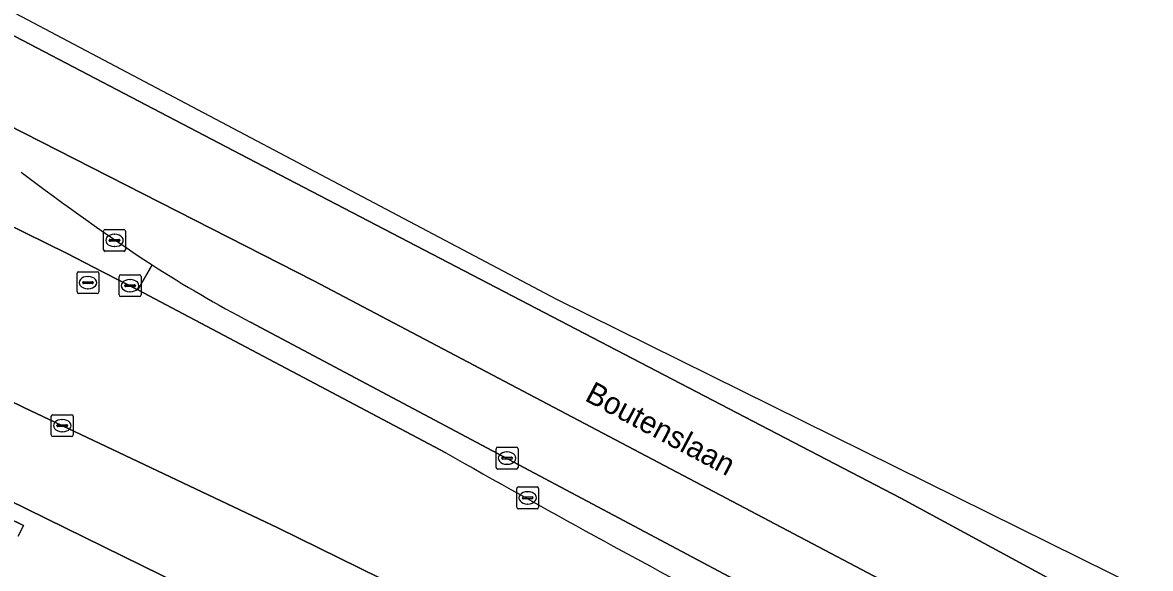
# Model space of a CAD drawing. Extents: x 160157 to 160921, y 381516 to 382045.
# Drawn here: x 160441.8 to 160493.3, y 381975.7 to 382000.7 of the extents above; entities that cross this region are included whole.
import ezdxf

# ---------------------------------------------------------------- set-up
doc = ezdxf.new("R2010")
doc.units = 0
for name, color, linetype in [('IMGEO_Berm_open', 7, 'Continuous'), ('IMGEO_Erf', 7, 'Continuous'), ('IMGEO_Kolk', 7, 'Continuous'), ('IMGEO_Openbare_ruimte_label', 7, 'Continuous'), ('IMGEO_Pand', 7, 'Continuous'), ('IMGEO_Rijbaan_lokaal_open', 7, 'Continuous'), ('IMGEO_Rijbaan_regionaal_gesloten', 7, 'Continuous'), ('IMGEO_Rioolput', 7, 'Continuous'), ('IMGEO_Verkeerseiland_groen', 7, 'Continuous'), ('IMGEO_Voetpad_open', 7, 'Continuous')]:
    doc.layers.add(name, color=color, linetype=linetype)

msp = doc.modelspace()

# ---------------------------------------------------------------- linework, layer by layer
at = {"layer": 'IMGEO_Berm_open'}
for points in [[(160447.738, 381989.6), (160447.085, 381988.461), (160461.163, 381981.009)], [(160474.789, 381973.536), (160500, 381960.326), (160522.19, 381948.698), (160522.991, 381948.067), (160523.654, 381949.34), (160513.241, 381954.71), (160502.844, 381960.063), (160500, 381961.576), (160494.279, 381964.619), (160452.239, 381986.977)]]:
    msp.add_lwpolyline(points, dxfattribs=at)
for centre, radius, start, end in [((160482.414, 382043.931), 64.454, 237.45198, 242.08423), ((160725.425, 382446.696), 535.443, 240.42651, 242.08952)]:
    msp.add_arc(centre, radius, start, end, dxfattribs=at)
at = {"layer": 'IMGEO_Erf'}
for points in [[(160499.613, 381930.156), (160499.728, 381932.119), (160500, 381935.142), (160500.334, 381938.849), (160504.716, 381938.591), (160504.68, 381937.97), (160512.664, 381937.5), (160512.953, 381943.6), (160501.945, 381949.103), (160497.103, 381938.644), (160494.055, 381942.41), (160498.282, 381950.798), (160402.448, 381997.893)], [(160426.28, 381985.318), (160441.863, 381977.687), (160441.625, 381977.202)]]:
    msp.add_lwpolyline(points, dxfattribs=at)
at = {"layer": 'IMGEO_Kolk'}
for p, q in [((160445.523, 381990.294), (160445.523, 381991.146)), ((160445.598, 381991.22), (160446.45, 381991.22)), ((160446.524, 381991.146), (160446.524, 381990.294)), ((160445.782, 381990.714), (160445.782, 381990.726)), ((160446.22, 381990.677), (160445.822, 381990.677)), ((160445.825, 381990.763), (160446.223, 381990.763)), ((160446.011, 381991), (160446.036, 381991)), ((160446.266, 381990.726), (160446.266, 381990.714)), ((160446.45, 381990.22), (160445.598, 381990.22)), ((160446.034, 381990.44), (160446.009, 381990.44)), ((160446.234, 381988.225), (160446.234, 381989.077)), ((160446.309, 381989.151), (160447.161, 381989.151)), ((160447.235, 381989.077), (160447.235, 381988.225)), ((160446.493, 381988.645), (160446.493, 381988.657)), ((160446.931, 381988.608), (160446.533, 381988.608)), ((160446.536, 381988.694), (160446.934, 381988.694)), ((160446.722, 381988.931), (160446.747, 381988.931)), ((160446.977, 381988.657), (160446.977, 381988.645)), ((160447.161, 381988.151), (160446.309, 381988.151)), ((160446.745, 381988.371), (160446.72, 381988.371)), ((160443.136, 381981.83), (160443.136, 381982.682)), ((160443.211, 381982.756), (160444.063, 381982.756)), ((160443.624, 381982.536), (160443.649, 381982.536)), ((160444.137, 381982.682), (160444.137, 381981.83)), ((160443.395, 381982.25), (160443.395, 381982.262)), ((160443.833, 381982.213), (160443.435, 381982.213)), ((160443.438, 381982.299), (160443.836, 381982.299)), ((160443.647, 381981.976), (160443.622, 381981.976)), ((160443.879, 381982.262), (160443.879, 381982.25)), ((160444.063, 381981.756), (160443.211, 381981.756)), ((160463.454, 381980.346), (160463.454, 381981.198)), ((160463.529, 381981.272), (160464.381, 381981.272)), ((160463.942, 381981.052), (160463.967, 381981.052)), ((160464.455, 381981.198), (160464.455, 381980.346)), ((160463.713, 381980.766), (160463.713, 381980.778)), ((160464.151, 381980.729), (160463.753, 381980.729)), ((160463.756, 381980.815), (160464.154, 381980.815)), ((160463.965, 381980.492), (160463.94, 381980.492)), ((160464.197, 381980.778), (160464.197, 381980.766)), ((160464.381, 381980.272), (160463.529, 381980.272)), ((160464.396, 381978.529), (160464.396, 381979.381)), ((160464.471, 381979.455), (160465.323, 381979.455)), ((160465.397, 381979.381), (160465.397, 381978.529)), ((160464.655, 381978.949), (160464.655, 381978.961)), ((160465.093, 381978.912), (160464.695, 381978.912)), ((160464.698, 381978.998), (160465.096, 381978.998)), ((160464.884, 381979.235), (160464.909, 381979.235)), ((160465.139, 381978.961), (160465.139, 381978.949)), ((160465.323, 381978.455), (160464.471, 381978.455)), ((160464.907, 381978.675), (160464.882, 381978.675))]:
    msp.add_line(p, q, dxfattribs=at)
for points in [[(160445.523, 381990.294), (160445.523, 381991.146)], [(160445.598, 381991.22), (160446.45, 381991.22)], [(160446.524, 381991.146), (160446.524, 381990.294)], [(160446.45, 381990.22), (160445.598, 381990.22)], [(160446.234, 381988.225), (160446.234, 381989.077)], [(160446.309, 381989.151), (160447.161, 381989.151)], [(160447.235, 381989.077), (160447.235, 381988.225)], [(160447.161, 381988.151), (160446.309, 381988.151)], [(160443.136, 381981.83), (160443.136, 381982.682)], [(160443.211, 381982.756), (160444.063, 381982.756)], [(160444.137, 381982.682), (160444.137, 381981.83)], [(160444.063, 381981.756), (160443.211, 381981.756)], [(160463.454, 381980.346), (160463.454, 381981.198)], [(160463.529, 381981.272), (160464.381, 381981.272)], [(160464.455, 381981.198), (160464.455, 381980.346)], [(160464.381, 381980.272), (160463.529, 381980.272)], [(160464.396, 381978.529), (160464.396, 381979.381)], [(160464.471, 381979.455), (160465.323, 381979.455)], [(160465.397, 381979.381), (160465.397, 381978.529)], [(160465.323, 381978.455), (160464.471, 381978.455)]]:
    msp.add_lwpolyline(points, dxfattribs=at)
for centre, radius, start, end in [((160445.6, 381991.144), 0.0765, 91.552, 178.448), ((160445.6, 381991.144), 0.0765, 91.552, 178.448), ((160446.448, 381991.144), 0.0765, 1.552, 88.448), ((160446.448, 381991.144), 0.0765, 1.552, 88.448), ((160445.822, 381990.723), 0.0403, 85.8775, 175.7526), ((160445.819, 381990.713), 0.0366, 178.938, 274.7102), ((160446.223, 381990.72), 0.043, 264.8664, 352.4533), ((160446.227, 381990.725), 0.0386, 1.7309, 96.639), ((160445.6, 381990.296), 0.0765, 181.552, 268.448), ((160445.6, 381990.296), 0.0765, 181.552, 268.448), ((160446.448, 381990.296), 0.0765, 271.552, 358.448), ((160446.448, 381990.296), 0.0765, 271.552, 358.448), ((160446.311, 381989.075), 0.0765, 91.552, 178.448), ((160446.311, 381989.075), 0.0765, 91.552, 178.448), ((160447.159, 381989.075), 0.0765, 1.552, 88.448), ((160447.159, 381989.075), 0.0765, 1.552, 88.448), ((160446.533, 381988.654), 0.0403, 85.8775, 175.7526), ((160446.53, 381988.644), 0.0366, 178.938, 274.7102), ((160446.934, 381988.651), 0.043, 264.8664, 352.4533), ((160446.938, 381988.656), 0.0386, 1.7309, 96.639), ((160446.311, 381988.227), 0.0765, 181.552, 268.448), ((160446.311, 381988.227), 0.0765, 181.552, 268.448), ((160447.159, 381988.227), 0.0765, 271.552, 358.448), ((160447.159, 381988.227), 0.0765, 271.552, 358.448), ((160443.213, 381982.68), 0.0765, 91.552, 178.448), ((160443.213, 381982.68), 0.0765, 91.552, 178.448), ((160444.061, 381982.68), 0.0765, 1.552, 88.448), ((160444.061, 381982.68), 0.0765, 1.552, 88.448), ((160443.435, 381982.259), 0.0403, 85.8775, 175.7526), ((160443.432, 381982.249), 0.0366, 178.938, 274.7102), ((160443.836, 381982.256), 0.043, 264.8664, 352.4533), ((160443.84, 381982.261), 0.0386, 1.7309, 96.639), ((160443.213, 381981.832), 0.0765, 181.552, 268.448), ((160443.213, 381981.832), 0.0765, 181.552, 268.448), ((160444.061, 381981.832), 0.0765, 271.552, 358.448), ((160444.061, 381981.832), 0.0765, 271.552, 358.448), ((160463.531, 381981.196), 0.0765, 91.552, 178.448), ((160463.531, 381981.196), 0.0765, 91.552, 178.448), ((160464.379, 381981.196), 0.0765, 1.552, 88.448), ((160464.379, 381981.196), 0.0765, 1.552, 88.448), ((160463.531, 381980.348), 0.0765, 181.552, 268.448), ((160463.531, 381980.348), 0.0765, 181.552, 268.448), ((160463.753, 381980.775), 0.0403, 85.8775, 175.7526), ((160463.75, 381980.765), 0.0366, 178.938, 274.7102), ((160464.154, 381980.772), 0.043, 264.8664, 352.4533), ((160464.158, 381980.777), 0.0386, 1.7309, 96.639), ((160464.379, 381980.348), 0.0765, 271.552, 358.448), ((160464.379, 381980.348), 0.0765, 271.552, 358.448), ((160464.473, 381979.379), 0.0765, 91.552, 178.448), ((160464.473, 381979.379), 0.0765, 91.552, 178.448), ((160465.321, 381979.379), 0.0765, 1.552, 88.448), ((160465.321, 381979.379), 0.0765, 1.552, 88.448), ((160464.695, 381978.958), 0.0403, 85.8775, 175.7526), ((160464.692, 381978.948), 0.0366, 178.938, 274.7102), ((160465.096, 381978.955), 0.043, 264.8664, 352.4533), ((160465.1, 381978.96), 0.0386, 1.7309, 96.639), ((160464.473, 381978.531), 0.0765, 181.552, 268.448), ((160464.473, 381978.531), 0.0765, 181.552, 268.448), ((160465.321, 381978.531), 0.0765, 271.552, 358.448), ((160465.321, 381978.531), 0.0765, 271.552, 358.448)]:
    msp.add_arc(centre, radius, start, end, dxfattribs=at)
for centre, major_axis, ratio, start_param, end_param in [((160446.01, 381990.72), (-0.387, 0.002), 0.722429, 4.712389, 7.853982), ((160446.035, 381990.72), (-0.39, 0.002), 0.717154, 1.570796, 4.712389), ((160446.721, 381988.651), (-0.387, 0.002), 0.722429, 4.712389, 7.853982), ((160446.746, 381988.651), (-0.39, 0.002), 0.717154, 1.570796, 4.712389), ((160443.623, 381982.256), (-0.387, 0.002), 0.722429, 4.712389, 7.853982), ((160443.648, 381982.256), (-0.39, 0.002), 0.717154, 1.570796, 4.712389), ((160463.941, 381980.772), (-0.387, 0.002), 0.722429, 4.712389, 7.853982), ((160463.966, 381980.772), (-0.39, 0.002), 0.717154, 1.570796, 4.712389), ((160464.883, 381978.955), (-0.387, 0.002), 0.722429, 4.712389, 7.853982), ((160464.908, 381978.955), (-0.39, 0.002), 0.717154, 1.570796, 4.712389)]:
    msp.add_ellipse(centre, major_axis=major_axis, ratio=ratio, start_param=start_param, end_param=end_param, dxfattribs=at)
at = {"layer": 'IMGEO_Pand'}
msp.add_lwpolyline([(160441.625, 381977.202), (160441.863, 381977.687), (160426.28, 381985.318)], dxfattribs=at)
at = {"layer": 'IMGEO_Rijbaan_lokaal_open'}
for points in [[(160447.085, 381988.461), (160445.476, 381989.29), (160443.866, 381990.117), (160423.757, 382000), (160407.842, 382007.822)], [(160399.863, 382003.519), (160404.804, 382001.246), (160407.395, 382000), (160413.942, 381996.852), (160428.582, 381989.594), (160441.879, 381983.091), (160453.485, 381977.588), (160461.898, 381973.443), (160463.584, 381972.567), (160476.354, 381965.933), (160479.961, 381964.048), (160500, 381953.649), (160515.073, 381945.818)], [(160461.163, 381981.009), (160447.085, 381988.461)]]:
    msp.add_lwpolyline(points, dxfattribs=at)
msp.add_arc((160725.425, 382446.696), 535.443, 240.42651, 242.08952, dxfattribs=at)
at = {"layer": 'IMGEO_Rijbaan_regionaal_gesloten'}
for points in [[(160640.692, 381901.715), (160520.062, 381961.392), (160504.185, 381969.247), (160466.234, 381988.022), (160419.184, 382012.886), (160365.751, 382037.141)], [(160581.541, 381928.321), (160555.806, 381940.957), (160530.995, 381953.177), (160502.017, 381968.051), (160497.302, 381970.609), (160481.941, 381978.945), (160475.912, 381982.085), (160452.111, 381994.482), (160435.823, 382003.008), (160421.334, 382010.113), (160410.064, 382015.797)], [(160410.064, 382015.797), (160421.334, 382010.113), (160435.823, 382003.008), (160452.111, 381994.482), (160475.912, 381982.085), (160481.941, 381978.945), (160497.302, 381970.609), (160502.017, 381968.051), (160530.995, 381953.177), (160555.806, 381940.957), (160581.541, 381928.321), (160591.887, 381923.241), (160619.539, 381909.789), (160639.905, 381900.067), (160640.692, 381901.715)], [(160413.304, 382010.083), (160428.844, 382002.405), (160433.281, 382000), (160455.129, 381988.874), (160485.491, 381972.871), (160495.708, 381967.479), (160514.358, 381957.638), (160540.324, 381944.763), (160582.108, 381924.035)], [(160582.108, 381924.035), (160540.324, 381944.763), (160514.358, 381957.638), (160495.708, 381967.479), (160485.491, 381972.871), (160455.129, 381988.874), (160433.281, 382000)], [(160452.239, 381986.977), (160494.279, 381964.619), (160500, 381961.576), (160502.844, 381960.063), (160513.241, 381954.71), (160523.654, 381949.34), (160531.89, 381945.298)]]:
    msp.add_lwpolyline(points, dxfattribs=at)
for centre, radius, start, end in [((160503.181, 382073.965), 100.953, 232.52977, 236.68768), ((160482.414, 382043.931), 64.454, 237.45198, 242.08423)]:
    msp.add_arc(centre, radius, start, end, dxfattribs=at)
at = {"layer": 'IMGEO_Rioolput'}
for p, q in [((160444.31, 381988.364), (160444.31, 381989.216)), ((160444.385, 381989.29), (160445.237, 381989.29)), ((160444.798, 381989.07), (160444.823, 381989.07)), ((160445.311, 381989.216), (160445.311, 381988.364)), ((160444.569, 381988.784), (160444.569, 381988.796)), ((160445.007, 381988.747), (160444.609, 381988.747)), ((160444.612, 381988.833), (160445.01, 381988.833)), ((160445.053, 381988.796), (160445.053, 381988.784)), ((160445.237, 381988.29), (160444.385, 381988.29)), ((160444.821, 381988.51), (160444.796, 381988.51))]:
    msp.add_line(p, q, dxfattribs=at)
for points in [[(160444.31, 381988.364), (160444.31, 381989.216)], [(160444.385, 381989.29), (160445.237, 381989.29)], [(160445.311, 381989.216), (160445.311, 381988.364)], [(160445.237, 381988.29), (160444.385, 381988.29)]]:
    msp.add_lwpolyline(points, dxfattribs=at)
for centre, radius, start, end in [((160444.387, 381989.214), 0.0765, 91.552, 178.448), ((160444.387, 381989.214), 0.0765, 91.552, 178.448), ((160445.235, 381989.214), 0.0765, 1.552, 88.448), ((160445.235, 381989.214), 0.0765, 1.552, 88.448), ((160444.609, 381988.793), 0.0403, 85.8775, 175.7526), ((160444.606, 381988.783), 0.0366, 178.938, 274.7102), ((160445.01, 381988.79), 0.043, 264.8664, 352.4533), ((160445.014, 381988.795), 0.0386, 1.7309, 96.639), ((160444.387, 381988.366), 0.0765, 181.552, 268.448), ((160444.387, 381988.366), 0.0765, 181.552, 268.448), ((160445.235, 381988.366), 0.0765, 271.552, 358.448), ((160445.235, 381988.366), 0.0765, 271.552, 358.448)]:
    msp.add_arc(centre, radius, start, end, dxfattribs=at)
for centre, major_axis, ratio, start_param, end_param in [((160444.797, 381988.79), (-0.387, 0.002), 0.722429, 4.712389, 7.853982), ((160444.822, 381988.79), (-0.39, 0.002), 0.717154, 1.570796, 4.712389)]:
    msp.add_ellipse(centre, major_axis=major_axis, ratio=ratio, start_param=start_param, end_param=end_param, dxfattribs=at)
at = {"layer": 'IMGEO_Verkeerseiland_groen'}
msp.add_lwpolyline([(160407.842, 382007.822), (160423.757, 382000), (160443.866, 381990.117), (160445.476, 381989.29), (160447.085, 381988.461), (160447.738, 381989.6)], dxfattribs=at)
msp.add_arc((160503.181, 382073.965), 100.953, 232.52977, 236.68768, dxfattribs=at)
at = {"layer": 'IMGEO_Voetpad_open'}
for points in [[(160441.879, 381983.091), (160428.582, 381989.594), (160413.942, 381996.852), (160407.395, 382000), (160404.804, 382001.246), (160399.863, 382003.519), (160378.965, 382013.132), (160357.444, 382022.211), (160355.89, 382018.493), (160357.59, 382017.782), (160358.953, 382017.212), (160359.146, 382017.608), (160358.163, 382018.089), (160358.403, 382018.579), (160373.026, 382011.418), (160374.008, 382010.938), (160374.001, 382010.924), (160378.888, 382008.882), (160397.931, 382000), (160402.448, 381997.893), (160498.282, 381950.798), (160501.945, 381949.103), (160512.953, 381943.6), (160518.133, 381941.164)], [(160463.584, 381972.567), (160461.898, 381973.443), (160453.485, 381977.588), (160441.879, 381983.091)]]:
    msp.add_lwpolyline(points, dxfattribs=at)

# ---------------------------------------------------------------- texts
at = {"layer": 'IMGEO_Openbare_ruimte_label'}
msp.add_text('Boutenslaan', height=1, rotation=331.9747, dxfattribs=at).set_placement((160467.456, 381983.427))

doc.saveas('drawing.dxf')
